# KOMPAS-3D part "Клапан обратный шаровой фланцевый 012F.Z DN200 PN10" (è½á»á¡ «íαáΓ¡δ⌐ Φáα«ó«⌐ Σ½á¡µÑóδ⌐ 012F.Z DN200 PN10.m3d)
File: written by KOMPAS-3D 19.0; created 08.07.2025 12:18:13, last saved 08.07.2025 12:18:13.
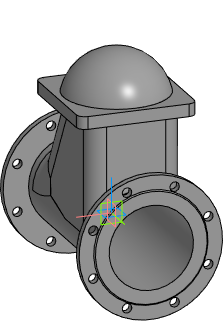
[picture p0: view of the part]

Document properties: Полное имя файла: E:\Dendor Работа Сачек\3D для проектировщиков\5.3 Тип 012F, 012F.Z Клапан обратный шаровой фланцевый\stp_Клапан обратный шаровой фланцевый 012F.Z PN10_16\Клапан обратный шаровой фланцевый 012F.Z DN200 PN10.m3d

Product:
- Part/product: Клапан обратный шаровой фланцевый 012F.Z DN200 PN10

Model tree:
1. Операция без истории:1  (labels: Клапан обратный шаровой фланцевый 012F.Z DN200 PN10)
